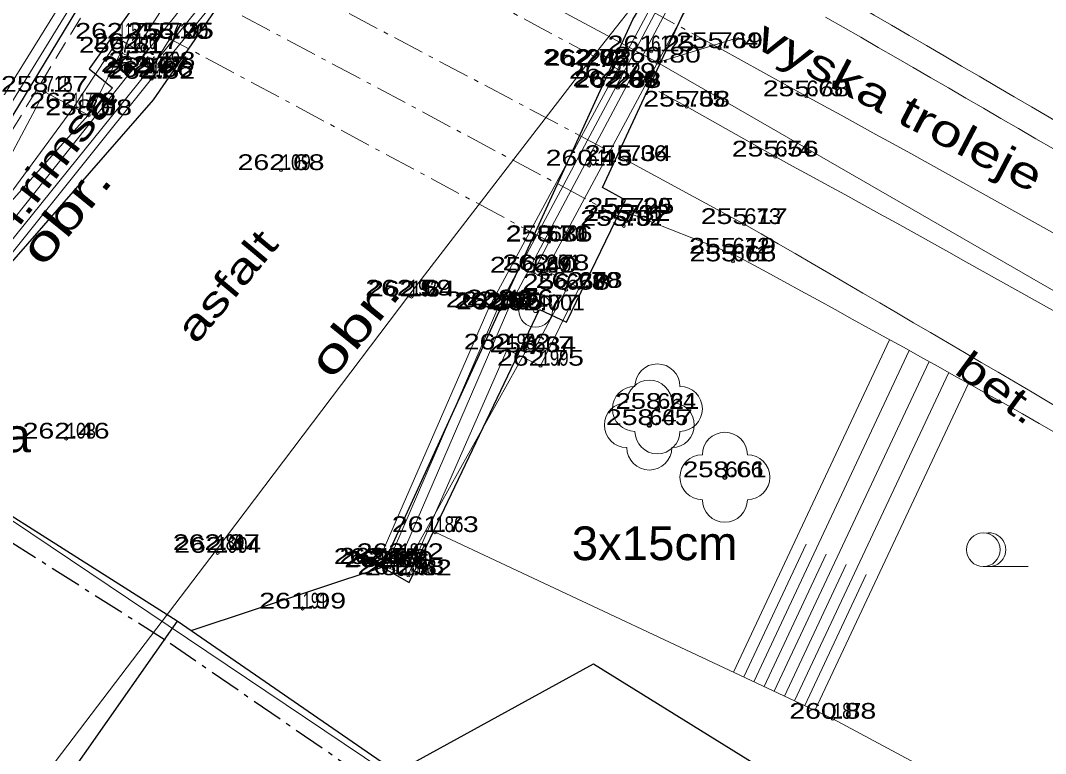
# Model space of a CAD drawing. Extents: x -568530 to -568223, y -1154101 to -1153740.
# Drawn here: x -568424.7 to -568401.91, y -1153942.5 to -1153926.2 of the extents above; entities that cross this region are included whole.
import ezdxf
from ezdxf.enums import TextEntityAlignment as Align

# ---------------------------------------------------------------- set-up
doc = ezdxf.new("R2010")
doc.units = 0
doc.header["$LTSCALE"] = 0.14
doc.header["$PDMODE"] = 32
doc.header["$PDSIZE"] = 0.07
doc.linetypes.add('DOT_DASHED', pattern=[7.7, 5, -1.2, 0.3, -1.2])
doc.linetypes.add('MEDIUM_DASHED', pattern=[4.5, 3, -1.5])
for name, color, linetype, lineweight in [('1', 7, 'Continuous', 25), ('10', 7, 'Continuous', 13), ('11', 7, 'Continuous', 13), ('12', 7, 'Continuous', 13), ('14', 7, 'Continuous', 13), ('15', 7, 'Continuous', 13), ('21', 7, 'Continuous', 13), ('22', 7, 'Continuous', 13), ('23', 7, 'Continuous', 13), ('36', 7, 'Continuous', 13), ('4', 7, 'Continuous', 25), ('42', 7, 'Continuous', 13), ('48', 7, 'Continuous', 13), ('52', 7, 'Continuous', 13), ('53', 7, 'Continuous', 13), ('54', 7, 'MEDIUM_DASHED', 13), ('6', 7, 'DOT_DASHED', 25), ('9', 7, 'Continuous', 13)]:
    doc.layers.add(name, color=color, linetype=linetype, lineweight=lineweight)
doc.layers.add('13', color=7, linetype='Continuous')
doc.layers.add('40', color=7, linetype='Continuous')

msp = doc.modelspace()

# ---------------------------------------------------------------- linework, layer by layer
at = {"layer": '1'}
for points in [[(-568474.2, -1153983.6), (-568452.46, -1153957.65), (-568449.01, -1153953.16), (-568441.85, -1153945.56), (-568434.01, -1153937.23), (-568430.2, -1153935.69), (-568428.09, -1153933.47), (-568426.88, -1153931.62), (-568414.57, -1153911.32), (-568413.31, -1153909.52)], [(-568421.22, -1153939.56), (-568428.14, -1153935.17), (-568430.26, -1153937.4), (-568443.63, -1153952.29), (-568447.7, -1153956.78), (-568470.49, -1153981.39)], [(-568416.35, -1153942.92), (-568421.22, -1153939.56), (-568427.43, -1153948.41), (-568440.04, -1153964.5), (-568454.41, -1153985.19), (-568457.74, -1153989.19)]]:
    msp.add_lwpolyline(points, dxfattribs=at)
at = {"layer": '10'}
for points in [[(-568427.22, -1153934.12), (-568426.3, -1153933.12), (-568421.79, -1153927.5), (-568420.4, -1153925.8), (-568418.54, -1153922.37), (-568415.81, -1153917.41), (-568415.26, -1153916.18), (-568415.38, -1153916.1)], [(-568403.6, -1153916.28), (-568408.01, -1153921.83), (-568409.54, -1153923.75), (-568411.54, -1153927.5), (-568414.28, -1153932.58), (-568416.77, -1153938.29), (-568416.57, -1153938.36)], [(-568416.07, -1153932.32), (-568412.12, -1153927.19), (-568410.48, -1153925.11)], [(-568451.7, -1153980.29), (-568449.61, -1153977.28), (-568446.84, -1153973.45), (-568445.91, -1153972.15), (-568442.46, -1153967.27), (-568439.57, -1153963.38), (-568433.28, -1153955), (-568432.53, -1153954), (-568431.81, -1153953.03), (-568426.84, -1153946.5), (-568420.35, -1153937.98), (-568416.07, -1153932.32)]]:
    msp.add_lwpolyline(points, dxfattribs=at)
at = {"layer": '11', "linetype": 'DOT_DASHED'}
for p, q in [((-568421.41, -1153923.93), (-568411.19, -1153929.33)), ((-568421.78, -1153925.03), (-568411.22, -1153930.66)), ((-568412.95, -1153931.12), (-568421.38, -1153926.61))]:
    msp.add_line(p, q, dxfattribs=at)
at = {"layer": '11'}
for p, q in [((-568408.61, -1153930.73), (-568411.19, -1153929.33)), ((-568413.442, -1153933.51), (-568416.24, -1153938.52)), ((-568413.442, -1153933.51), (-568413.31, -1153933.58))]:
    msp.add_line(p, q, dxfattribs=at)
for points in [[(-568427.06, -1153932.94), (-568426.57, -1153933.16), (-568421.91, -1153927.38), (-568420.56, -1153925.69), (-568418.7, -1153922.26), (-568415.95, -1153917.33), (-568415.38, -1153916.1), (-568413.01, -1153910.69), (-568413.35, -1153910.47), (-568413.53, -1153910.7), (-568415.82, -1153915.8), (-568416.54, -1153915.43), (-568417.52, -1153917.26), (-568416.8, -1153917.63), (-568420.348, -1153924.07), (-568422.13, -1153926.84), (-568422.52, -1153926.61), (-568423.54, -1153928.16)], [(-568416.57, -1153938.36), (-568416.08, -1153938.54), (-568413.88, -1153933.52), (-568413.14, -1153933.88), (-568412.28, -1153932.15), (-568413.02, -1153931.76), (-568408.62, -1153923.56), (-568407.79, -1153922.53), (-568407.25, -1153922.82), (-568406.24, -1153920.96), (-568405.9, -1153920.45), (-568403.04, -1153916.71), (-568403.47, -1153916.36), (-568407.9, -1153921.95), (-568409.42, -1153923.82), (-568411.46, -1153927.67), (-568414.09, -1153932.6)]]:
    msp.add_lwpolyline(points, close=True, dxfattribs=at)
for points in [[(-568427.75, -1153932.6), (-568427.58, -1153932.35), (-568427.39, -1153932.06), (-568422.46, -1153924.05)], [(-568426.74, -1153932.62), (-568424.17, -1153927.79), (-568423.19, -1153928.31), (-568422.47, -1153926.92), (-568421.78, -1153927.25), (-568421.38, -1153926.61)], [(-568411.22, -1153930.66), (-568411.13, -1153930.5), (-568408.87, -1153931.39)], [(-568412.95, -1153931.12), (-568413.3, -1153931.81), (-568412.57, -1153932.19), (-568413.31, -1153933.58)]]:
    msp.add_lwpolyline(points, dxfattribs=at)
for centre, radius, start, end in [((-569009.5906, -1154964.079), 1200.8724, 58.47781, 59.85365), ((-568847.5367, -1154693.8111), 885.2023, 58.27428, 60.13925), ((-568987.7107, -1154929.3603), 1154.3916, 58.50566, 59.89077), ((-568598.8116, -1154282.7187), 399.3866, 57.62556, 61.60266)]:
    msp.add_arc(centre, radius, start, end, dxfattribs=at)
for p in [(-568422.52, -1153926.61), (-568421.38, -1153926.61), (-568421.37, -1153926.6), (-568422.47, -1153926.92), (-568422.13, -1153926.84), (-568410.68, -1153926.89), (-568409.16, -1153926.82), (-568410.54, -1153927.14), (-568421.95, -1153927.35), (-568421.91, -1153927.38), (-568421.78, -1153927.25), (-568412.12, -1153927.19), (-568412.08, -1153927.21), (-568421.83, -1153927.46), (-568421.79, -1153927.5), (-568411.54, -1153927.5), (-568424.17, -1153927.79), (-568411.46, -1153927.67), (-568411.42, -1153927.7), (-568407.23, -1153927.89), (-568423.54, -1153928.16), (-568423.19, -1153928.31), (-568409.89, -1153928.12), (-568412.06, -1153929.43), (-568411.19, -1153929.33), (-568407.92, -1153929.23), (-568418.91, -1153929.53), (-568411.13, -1153930.5), (-568411.29, -1153930.77), (-568411.22, -1153930.66), (-568408.61, -1153930.73), (-568412.97, -1153931.11), (-568412.95, -1153931.12), (-568408.87, -1153931.39), (-568408.86, -1153931.56), (-568413.3, -1153931.81), (-568413.02, -1153931.76), (-568412.28, -1153932.15), (-568416.07, -1153932.32), (-568416.01, -1153932.34), (-568412.57, -1153932.19), (-568414.28, -1153932.58), (-568414.09, -1153932.6), (-568414.05, -1153932.63), (-568413.82, -1153932.54), (-568413.88, -1153933.52), (-568413.31, -1153933.58), (-568413.14, -1153933.88), (-568410.54, -1153934.84), (-568410.72, -1153935.2), (-568423.69, -1153935.5), (-568409.04, -1153936.36), (-568415.48, -1153937.58), (-568420.35, -1153937.98), (-568420.32, -1153938.04), (-568416.77, -1153938.29), (-568416.68, -1153938.28), (-568416.26, -1153938.18), (-568416.57, -1153938.36), (-568416.5, -1153938.35), (-568416.24, -1153938.52), (-568416.08, -1153938.54), (-568418.43, -1153939.28), (-568406.64, -1153941.73)]:
    msp.add_point(p, dxfattribs=at)
at = {"layer": '12'}
for p, q in [((-568409.16, -1153926.82), (-568407.23, -1153927.89)), ((-568409.89, -1153928.12), (-568407.92, -1153929.23))]:
    msp.add_line(p, q, dxfattribs=at)
at = {"layer": '12', "linetype": 'DOT_DASHED'}
for centre, radius, start, end in [((-568674.5323, -1154411.701), 552.7495, 61.30839, 62.56881), ((-568667.9439, -1154402.5275), 540.0503, 61.45602, 62.73461)]:
    msp.add_arc(centre, radius, start, end, dxfattribs=at)
at = {"layer": '12'}
for centre, radius, start, end in [((-568635.0051, -1154346.2032), 476.306, 58.03243, 61.43134), ((-568645.0661, -1154364.1594), 495.3805, 58.1384, 61.39848)]:
    msp.add_arc(centre, radius, start, end, dxfattribs=at)
at = {"layer": '14'}
msp.add_lwpolyline([(-568415.48, -1153937.58), (-568406.64, -1153941.73), (-568392.63, -1153949.25), (-568382.59, -1153955.78), (-568371.09, -1153963.05), (-568356.19, -1153973.32)], dxfattribs=at)
at = {"layer": '15'}
for p, q in [((-568408.847, -1153940.694), (-568405.376, -1153933.302)), ((-568408.394, -1153940.907), (-568404.938, -1153933.544)), ((-568407.941, -1153941.119), (-568404.5, -1153933.788)), ((-568407.489, -1153941.332), (-568404.062, -1153934.032)), ((-568407.036, -1153941.544), (-568403.625, -1153934.277)), ((-568408.62, -1153940.8), (-568407.235, -1153937.849)), ((-568408.168, -1153941.013), (-568406.788, -1153938.074)), ((-568407.715, -1153941.225), (-568406.341, -1153938.299)), ((-568407.262, -1153941.438), (-568405.895, -1153938.524))]:
    msp.add_line(p, q, dxfattribs=at)
at = {"layer": '21'}
for radius in [0.375, 0.05]:
    msp.add_circle((-568413.25, -1153932.65), radius, dxfattribs=at)
at = {"layer": '22'}
for centre in [(-568410.54, -1153934.84), (-568410.72, -1153935.2), (-568409.04, -1153936.36)]:
    msp.add_circle(centre, 0.05, dxfattribs=at)
for centre, start, end in [((-568410.54, -1153934.34), 0, 180), ((-568410.72, -1153934.7), 0, 180), ((-568411.04, -1153934.84), 90, 270), ((-568410.04, -1153934.84), 270, 90), ((-568411.22, -1153935.2), 90, 270), ((-568410.22, -1153935.2), 270, 90), ((-568410.54, -1153935.34), 180, 0), ((-568409.04, -1153935.86), 0, 180), ((-568410.72, -1153935.7), 180, 0), ((-568409.54, -1153936.36), 90, 270), ((-568408.54, -1153936.36), 270, 90), ((-568409.04, -1153936.86), 180, 0)]:
    msp.add_arc(centre, 0.5, start, end, dxfattribs=at)
at = {"layer": '36'}
msp.add_line((-568403.292, -1153938.347), (-568402.292, -1153938.347), dxfattribs=at)
msp.add_circle((-568403.292, -1153937.9721), 0.375, dxfattribs=at)
msp.add_arc((-568403.167, -1153937.9721), 0.375, 260.40593, 99.59407, dxfattribs=at)
at = {"layer": '4'}
msp.add_line((-568420.91, -1153939.77), (-568416.66, -1153938.36), dxfattribs=at)
for points in [[(-568428.14, -1153935.17), (-568426.33, -1153933.21), (-568421.75, -1153927.97), (-568418.17, -1153922.79), (-568416.21, -1153919.02), (-568412.97, -1153910.63), (-568413.31, -1153909.52)], [(-568413.82, -1153910.25), (-568413.59, -1153911.09), (-568414.86, -1153913.82), (-568415.35, -1153913.69), (-568416.55, -1153916.32), (-568416.14, -1153916.59), (-568417.09, -1153919.02), (-568418.88, -1153922.45), (-568420.8, -1153925.07), (-568421.36, -1153924.73), (-568423.18, -1153927.28), (-568422.66, -1153927.7), (-568426.27, -1153931.74), (-568426.66, -1153932.38), (-568426.33, -1153933.21)], [(-568416.66, -1153938.36), (-568411.09, -1153926.18), (-568408.89, -1153922.6), (-568403.83, -1153916.49), (-568364.99, -1153940.47), (-568354.7, -1153940.43), (-568327.96, -1153959.28), (-568308.58, -1153974.27), (-568269.22, -1154006.01)], [(-568416.66, -1153938.36), (-568416.06, -1153938.7), (-568413.16, -1153932.63), (-568412.56, -1153932.91), (-568411.25, -1153930.2), (-568411.76, -1153929.92), (-568409.62, -1153925.3), (-568407, -1153921.99), (-568406.54, -1153922.36), (-568404.34, -1153919.52), (-568404.76, -1153919.24), (-568402.95, -1153917.03)], [(-568416.35, -1153942.92), (-568411.96, -1153940.51), (-568386.96, -1153956.01), (-568354.94, -1153977.29), (-568293.66, -1154026.45)]]:
    msp.add_lwpolyline(points, dxfattribs=at)
at = {"layer": '48'}
msp.add_line((-568410.54, -1153927.14), (-568408.732, -1153926.583), dxfattribs=at)
at = {"layer": '52'}
msp.add_lwpolyline([(-568440.61, -1153926.76), (-568414.88, -1153944.05), (-568397.12, -1153956.51), (-568380.33, -1153967.93), (-568365.972, -1153978.132)], dxfattribs=at)
at = {"layer": '53'}
msp.add_lwpolyline([(-568433.578, -1153915.068), (-568419.78, -1153922.17), (-568410.54, -1153927.14), (-568389.55, -1153939.23), (-568371.805, -1153950.061), (-568349.435, -1153965.343)], dxfattribs=at)
at = {"layer": '54'}
msp.add_lwpolyline([(-568427.2, -1153932.43), (-568413.84, -1153910.52), (-568413.84, -1153910.52)], dxfattribs=at)
at = {"layer": '6'}
msp.add_line((-568421.49, -1153939.98), (-568428.41, -1153935.59), dxfattribs=at)
msp.add_lwpolyline([(-568421.91, -1153949.41), (-568417.06, -1153943.03), (-568421.5, -1153939.97)], dxfattribs=at)
at = {"layer": '9'}
for points in [[(-568427.829, -1153932.308), (-568414.062, -1153910.116), (-568413.58, -1153909.34)], [(-568413.29, -1153910.8), (-568416.08, -1153917.08), (-568420.68, -1153925.36), (-568426.72, -1153932.96)], [(-568416.26, -1153938.18), (-568413.82, -1153932.54), (-568409.29, -1153924.02), (-568403.36, -1153916.6)]]:
    msp.add_lwpolyline(points, dxfattribs=at)

# ---------------------------------------------------------------- texts
at = {"layer": '12'}
for s, width, p in [('262.75', 1.35, (-568422.5205, -1153926.61)), ('255.95', 1.35, (-568421.3805, -1153926.61)), ('258.75', 1.35, (-568421.3705, -1153926.6)), ('256.61', 1.3, (-568422.47, -1153926.92)), ('262.77', 1.35, (-568422.13, -1153926.84)), ('261.25', 1.35, (-568410.6805, -1153926.89)), ('255.69', 1.35, (-568409.16, -1153926.82)), ('256.58', 1.35, (-568421.78, -1153927.25)), ('262.76', 1.35, (-568412.12, -1153927.19)), ('262.82', 1.35, (-568412.08, -1153927.21)), ('260.80', 1.35, (-568410.5395, -1153927.14)), ('262.77', 1.35, (-568421.95, -1153927.35)), ('262.67', 1.35, (-568421.91, -1153927.38)), ('262.66', 1.35, (-568421.83, -1153927.46)), ('262.62', 1.35, (-568421.79, -1153927.5)), ('262.79', 1.35, (-568411.54, -1153927.5)), ('262.80', 1.35, (-568411.4595, -1153927.67)), ('262.88', 1.35, (-568411.42, -1153927.7)), ('258.27', 1.35, (-568424.17, -1153927.79)), ('255.68', 1.35, (-568407.23, -1153927.89)), ('262.72', 1.35, (-568423.54, -1153928.16)), ('255.58', 1.35, (-568409.89, -1153928.12)), ('258.08', 1.35, (-568423.19, -1153928.31)), ('255.56', 1.35, (-568407.92, -1153929.23)), ('262.68', 1.35, (-568418.91, -1153929.53)), ('260.45', 1.35, (-568412.0605, -1153929.43)), ('255.34', 1.35, (-568411.19, -1153929.33)), ('255.32', 1.35, (-568411.22, -1153930.66)), ('255.25', 1.35, (-568411.1305, -1153930.5)), ('255.57', 1.35, (-568411.29, -1153930.77)), ('255.17', 1.35, (-568408.61, -1153930.73)), ('255.86', 1.35, (-568412.95, -1153931.12)), ('258.71', 1.3, (-568412.97, -1153931.11)), ('255.19', 1.35, (-568408.87, -1153931.39)), ('255.66', 1.35, (-568408.86, -1153931.56)), ('256.40', 1.35, (-568413.2995, -1153931.81)), ('262.78', 1.35, (-568413.02, -1153931.76)), ('256.58', 1.35, (-568412.57, -1153932.19)), ('262.78', 1.35, (-568412.28, -1153932.15)), ('262.59', 1.35, (-568416.07, -1153932.32)), ('262.64', 1.35, (-568416.01, -1153932.34)), ('262.65', 1.35, (-568414.2805, -1153932.58)), ('262.65', 1.35, (-568414.0905, -1153932.6)), ('262.75', 1.35, (-568414.0505, -1153932.63)), ('262.76', 1.35, (-568413.82, -1153932.54)), ('262.72', 1.35, (-568413.88, -1153933.52)), ('258.34', 1.35, (-568413.31, -1153933.58)), ('262.75', 1.35, (-568413.1405, -1153933.88)), ('258.21', 1.3, (-568410.54, -1153934.84)), ('258.47', 1.35, (-568410.72, -1153935.2)), ('262.46', 1.35, (-568423.69, -1153935.5)), ('258.61', 1.3, (-568409.04, -1153936.36)), ('261.73', 1.35, (-568415.48, -1153937.58)), ('262.37', 1.35, (-568420.35, -1153937.98)), ('262.44', 1.35, (-568420.32, -1153938.04)), ('262.62', 1.35, (-568416.26, -1153938.18)), ('262.15', 1.35, (-568416.7705, -1153938.29)), ('262.51', 1.3, (-568416.68, -1153938.28)), ('262.51', 1.3, (-568416.57, -1153938.36)), ('262.60', 1.35, (-568416.4995, -1153938.35)), ('261.98', 1.35, (-568416.24, -1153938.52)), ('262.62', 1.35, (-568416.08, -1153938.54)), ('261.99', 1.35, (-568418.43, -1153939.28)), ('260.88', 1.35, (-568406.64, -1153941.73))]:
    msp.add_text(s, height=0.35, dxfattribs=dict(at, width=width)).set_placement(p, align=Align.CENTER)
at = {"layer": '13'}
for s, width, p in [('115', 0.55, (-568422.52, -1153926.61)), ('720', 1.1, (-568421.38, -1153926.61)), ('713', 0.8, (-568421.37, -1153926.6)), ('718', 0.8, (-568422.47, -1153926.92)), ('116', 0.55, (-568422.13, -1153926.84)), ('612', 0.8, (-568410.68, -1153926.89)), ('704', 1.1, (-568409.16, -1153926.82)), ('719', 0.8, (-568421.78, -1153927.25)), ('202', 1.1, (-568412.12, -1153927.19)), ('203', 1.1, (-568412.08, -1153927.21)), ('1', 0.45, (-568410.54, -1153927.14)), ('114', 0.55, (-568421.95, -1153927.35)), ('113', 0.55, (-568421.91, -1153927.38)), ('112', 0.55, (-568421.83, -1153927.46)), ('111', 0.45, (-568421.79, -1153927.5)), ('212', 0.8, (-568411.54, -1153927.5)), ('204', 1.1, (-568411.46, -1153927.67)), ('205', 1.1, (-568411.42, -1153927.7)), ('715', 0.8, (-568424.17, -1153927.79)), ('675', 1.05, (-568407.23, -1153927.89)), ('117', 0.55, (-568423.54, -1153928.16)), ('705', 1.1, (-568409.89, -1153928.12)), ('717', 0.8, (-568423.19, -1153928.31)), ('674', 1.05, (-568407.92, -1153929.23)), ('109', 0.85, (-568418.91, -1153929.53)), ('611', 0.7, (-568412.06, -1153929.43)), ('706', 1.1, (-568411.19, -1153929.33)), ('700', 1.15, (-568411.13, -1153930.5)), ('702', 1.1, (-568411.29, -1153930.77)), ('673', 1.05, (-568408.61, -1153930.73)), ('610', 0.85, (-568412.97, -1153931.11)), ('670', 1.1, (-568412.95, -1153931.12)), ('672', 1.05, (-568408.87, -1153931.39)), ('669', 1.1, (-568413.3, -1153931.81)), ('668', 1.1, (-568412.57, -1153932.19)), ('200', 1.15, (-568412.28, -1153932.15)), ('192', 0.8, (-568416.07, -1153932.32)), ('193', 0.8, (-568416.01, -1153932.34)), ('196', 0.85, (-568414.28, -1153932.58)), ('194', 0.8, (-568414.09, -1153932.6)), ('195', 0.8, (-568414.05, -1153932.63)), ('197', 0.8, (-568413.82, -1153932.54)), ('198', 0.8, (-568413.88, -1153933.52)), ('667', 1.1, (-568413.31, -1153933.58)), ('199', 0.8, (-568413.14, -1153933.88)), ('664', 1.1, (-568410.54, -1153934.84)), ('665', 1.1, (-568410.72, -1153935.2)), ('108', 0.85, (-568423.69, -1153935.5)), ('666', 1.1, (-568409.04, -1153936.36)), ('186', 0.8, (-568415.48, -1153937.58)), ('189', 0.8, (-568420.35, -1153937.98)), ('190', 0.85, (-568420.32, -1153938.04)), ('184', 0.8, (-568416.26, -1153938.18)), ('180', 0.85, (-568416.77, -1153938.29)), ('181', 0.7, (-568416.68, -1153938.28)), ('182', 0.8, (-568416.57, -1153938.36)), ('183', 0.8, (-568416.5, -1153938.35)), ('185', 0.8, (-568416.24, -1153938.52)), ('188', 0.8, (-568416.08, -1153938.54)), ('191', 0.7, (-568418.43, -1153939.28)), ('187', 0.8, (-568406.64, -1153941.73))]:
    msp.add_text(s, height=0.35, dxfattribs=dict(at, width=width)).set_placement(p)
for s, p in [('701', (-568411.22, -1153930.66)), ('671', (-568408.86, -1153931.56)), ('201', (-568413.02, -1153931.76))]:
    msp.add_text(s, height=0.35, dxfattribs=at).set_placement(p)
at = {"layer": '22', "width": 1.35}
msp.add_text('262.77', height=0.35, dxfattribs=at).set_placement((-568413.25, -1153932.65), align=Align.CENTER)
at = {"layer": '23', "width": 1.05}
msp.add_text('4001', height=0.35, dxfattribs=at).set_placement((-568413.25, -1153932.65))
at = {"layer": '40', "width": 1.4}
for s, rotation, p in [('beton.rimsa', 52.209, (-568426.442, -1153932.999)), ('asfalt', 50.073, (-568420.803, -1153933.426)), ('bet.', 323.922, (-568403.966, -1153934.035))]:
    msp.add_text(s, height=0.65, rotation=rotation, dxfattribs=at).set_placement(p)
at = {"layer": '42', "width": 1.45}
for p in [(-568423.4091, -1153930.7448), (-568416.9901, -1153933.2468)]:
    msp.add_text('obr.', height=0.75, rotation=50.935, dxfattribs=at).set_placement(p, align=Align.CENTER)
at = {"layer": '42'}
for s, width, p in [('C09a', 1.1, (-568425.7905, -1153935.803)), ('3x15cm', 1.05, (-568410.601, -1153938.204))]:
    msp.add_text(s, height=0.75, dxfattribs=dict(at, width=width)).set_placement(p, align=Align.CENTER)
at = {"layer": '48', "width": 1.35}
msp.add_text('vyska troleje', height=0.7, rotation=332.317, dxfattribs=at).set_placement((-568405.3081, -1153928.4171), align=Align.CENTER)

doc.saveas('drawing.dxf')
